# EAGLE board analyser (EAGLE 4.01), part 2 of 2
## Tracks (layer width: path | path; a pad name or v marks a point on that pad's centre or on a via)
1A0
  Top 0.406: IC5.9 108.97,43.47 109.45,43 109.45,32.04 108.81,31.41 96.59,31.41 95.79,32.2 95.79,35.22 96.43,35.85 97.7,35.85 | 97.7,35.85 | 97.7,35.85 IC9.2
1A1
  Top 0.406: 101.35,46.49 108.18,46.49 | IC9.5 97.7,39.66 98.97,39.66 100.56,41.25 100.56,45.7 101.35,46.49 | 101.35,46.49 | 108.18,46.49 | IC5.7 112.46,42.2 108.18,46.49
1A2
  Top 0.406: IC9.11 93.41,40.93 95,39.35 95,31.88 96.27,30.61 109.13,30.61 110.24,31.73 110.24,38.87 112.3,40.93 113.73,40.93 IC5.6
1A3
  Top 0.406: IC9.14 93.09,37.12 94.21,36.01 94.21,31.57 95.95,29.82 109.45,29.82 111.03,31.41 111.03,38.23 | IC5.5 112.46,39.66 111.03,38.23 | 111.03,38.23
1A4
  Top 0.406: IC10.2 84.52,34.27 86.11,32.68 86.11,30.46 87.54,29.03 109.76,29.03 111.83,31.09 111.83,36.65 112.3,37.12 113.73,37.12 | 113.73,37.12 | 113.73,37.12 IC5.3
1A5
  Top 0.406: IC10.5 80.71,38.08 80.39,37.76 80.39,32.2 84.36,28.23 112.94,28.23 115.95,31.25 115.95,35.22 115.32,35.85 IC5.2 | IC5.2 113.57,35.85 | IC5.2
1A6
  Top 0.406: IC10.11 71.98,39.35 70.08,37.44 70.08,32.52 73.25,29.34 81.98,29.34 83.89,27.44 113.26,27.44 116.75,30.93 | IC5.4 113.73,38.39 | IC5.4 | IC5.4 115.32,38.39 116.75,36.96 116.75,30.93 | 116.75,30.93
1A7  (via drill 0.61 pad 1.68)
  Top 0.406: IC10.14 77.54,35.54 78.65,34.42 v78.65,30.93 | v105.16,38.39 IC5.13
  Bottom 0.406: v105.16,38.39 106.75,36.81 106.75,34.58 102.3,30.14 79.44,30.14 v78.65,30.93
1A8  (via drill 0.61 pad 1.68)
  Top 0.406: IC5.12 106.43,39.66 104.84,41.25 103.89,41.25 | v82.14,82.53 | IC11.2 83.25,81.42 v82.14,82.53 | 103.89,41.25 v103.73,41.25 | v103.73,41.25 | v103.73,41.25 | 103.89,41.25 v103.73,41.25
  Bottom 0.406: v103.73,41.25 105.16,42.68 105.16,60.94 83.57,82.53 v82.14,82.53
1A9  (via drill 0.61 pad 1.68)
  Top 0.406: IC5.14 106.27,37.12 105.95,36.81 104.68,36.81 103.73,37.76 103.73,38.23 v102.3,39.66 | IC11.5 82.94,77.61 82.46,77.13 82.46,72.21 v83.09,71.57
  Bottom 0.406: v83.09,71.57 84.52,70.14 94.84,70.14 104.37,60.62 104.37,44.11 | 104.37,44.11 | 104.37,44.11 | v102.3,39.66 102.3,42.04 104.37,44.11
1A10  (via drill 0.61 pad 1.68)
  Top 0.406: v105.16,35.38 105.64,35.85 IC5.15 | IC11.11 92.14,76.34 v93.09,77.29
  Bottom 0.406: v93.09,77.29 94.52,75.86 94.52,72.68 105.95,61.25 105.95,41.25 103.73,39.03 103.73,36.81 v105.16,35.38 | v105.16,35.38
1A11  (via drill 0.61 pad 1.68)
  Top 0.406: IC5.1 112.94,34.58 112.94,33 v113.89,32.04 | IC11.14 92.46,80.15 v93.09,79.51 | IC6.10 79.6,94.59 80.08,95.07 82.14,95.07 83.41,93.8 v83.41,87.61
  Bottom 0.406: v113.89,32.04 115,33.15 115,40.46 | v83.41,87.61 84.05,88.24 90.87,88.24 93.09,86.02 v93.09,79.51 119.29,53.32 119.29,44.74 115,40.46 | 115,40.46
1A12
  Top 0.406: 71.98,81.41 | 71.98,81.41 IC12.2 | 71.98,81.41 69.92,81.41 66.74,84.59 66.74,88.56 68.81,90.62 79.92,90.62 80.87,91.57 IC6.9 | IC6.9 80.87,93.32 | IC6.9
1A13
  Top 0.406: 71.66,77.6 | IC12.5 71.66,77.6 | 71.66,77.6 73.25,77.6 75.47,79.83 75.47,83.64 76.74,84.91 78.81,84.91 79.6,85.7 IC6.7
1C0
  Top 0.406: IC17.16 58.32,49.82 49.28,40.77 43.41,40.77 40.62,37.99 IC16.12
1C1
  Top 0.406: IC17.15 57.52,50.13 48.96,41.57 43.09,41.57 39.84,38.32 IC16.13
1D0
  Top 0.406: IC13.11 | IC13.11 92.46,54.27 91.03,55.7 67.06,55.7 64.84,53.47 62.3,53.47 60.72,55.05 IC17.19 | IC13.11 92.46,51.41 94.68,49.19 97.54,49.19 108.18,59.82 113.73,59.82 119.76,65.86 IC14.18 | 109.6,71.73 116.75,71.73 119.76,68.71 IC14.18 | 109.6,71.73 | IC15.4 109.6,71.73 | IC14.18
1D1
  Top 0.406: IC13.12 | IC13.12 93.73,54.27 91.51,56.49 66.74,56.49 64.52,54.27 62.61,54.27 61.52,55.36 IC17.20 | IC13.12 93.73,51.41 95.16,49.98 97.22,49.98 107.86,60.62 113.26,60.62 118.49,65.86 118.49,67.44 | IC15.3 105.48,70.46 105.95,70.94 109.92,70.94 | 109.92,70.94 116.27,70.94 118.49,68.71 118.49,67.44 | 109.92,70.94 | IC14.17 118.49,67.29 | 118.49,67.44 IC14.17 | IC14.17
1D2
  Top 0.406: 64.2,55.06 66.42,57.28 91.98,57.28 95,54.27 IC13.13 | IC13.13 | IC13.13 95,51.41 95.63,50.78 96.9,50.78 107.54,61.41 112.78,61.41 117.22,65.86 117.22,67.44 | IC15.2 105.48,69.19 106.43,70.14 110.24,70.14 | 110.24,70.14 115.8,70.14 117.22,68.71 117.22,67.44 | 110.24,70.14 | IC14.16 117.22,67.29 | 117.22,67.44 IC14.16 | IC14.16 | IC17.21 62.32,55.67 62.93,55.06 64.2,55.06 | 64.2,55.06
1D3
  Top 0.406: 96.27,61.89 92.46,58.08 63.12,58.08 IC17.22 | IC15.1 105.48,67.92 106.91,69.35 110.56,69.35 | 110.56,69.35 115.32,69.35 115.95,68.71 IC14.15 | 110.56,69.35 | 96.27,61.89 106.91,61.89 107.22,62.21 112.3,62.21 115.95,65.86 IC14.15 | 96.27,61.89 IC13.15 | IC14.15
1D4
  Top 0.406: 103.25,63.16 99.76,66.65 99.76,68.87 99.44,69.19 97.86,69.19 | 103.25,63.16 | IC14.14 114.68,65.86 111.83,63 103.41,63 103.25,63.16 | 97.86,69.19 96.59,69.19 95,67.6 IC13.16 95,61.89 91.95,58.84 IC17.23 | 97.86,69.19 98.02,69.19 IC15.15 97.86,69.19
1D5
  Top 0.406: 98.17,70.46 IC15.14 | 98.17,70.46 96.59,70.46 93.73,67.6 IC13.17 93.73,61.89 91.48,59.64 IC17.24 | 100.56,69.35 99.44,70.46 98.17,70.46 | IC14.13 113.41,65.86 111.35,63.79 103.73,63.79 100.56,66.97 100.56,69.35 | 100.56,69.35
1D6
  Top 0.406: IC15.13 98.17,71.73 | 98.17,71.73 96.59,71.73 92.46,67.6 IC13.18 92.46,61.89 91.01,60.44 IC17.25 | 102.94,65.7 101.35,67.29 101.35,69.83 99.44,71.73 98.17,71.73 | 102.94,65.7 | IC14.12 112.14,65.86 110.87,64.59 104.05,64.59 102.94,65.7
1D7
  Top 0.406: IC15.12 98.17,73 | 98.17,73 96.59,73 91.19,67.6 IC13.19 91.19,61.89 90.54,61.24 IC17.26 | 98.17,73 99.44,73 102.14,70.3 102.14,67.6 104.37,65.38 110.4,65.38 110.87,65.86 110.87,67.29 | 110.87,67.29 | 110.87,67.29 IC14.11
1G0
  Top 0.406: CON2.10 | CON2.10 | CON2.10 41.66,5.06 42.93,6.33 42.93,7.28 41.42,8.79 IC16.30
1G1
  Top 0.406: CON2.11 | CON2.11 | CON2.11 44.2,7.12 42.22,9.1 IC16.31
1G2
  Top 0.406: CON2.12 | CON2.12 | CON2.12 46.74,5.69 43.02,9.41 IC16.32
1G3
  Top 0.406: CON2.13 | CON2.13 | CON2.13 49.28,5.69 47.06,7.91 47.06,10.45 45.88,11.63 IC16.1
1G4
  Top 0.406: CON2.14 | CON2.14 | CON2.14 51.82,4.26 47.85,8.23 47.85,10.77 46.19,12.43 IC16.2
1G5
  Top 0.406: CON2.15 | CON2.15 | CON2.15 54.36,4.26 57.85,7.75 57.85,19.66 54.36,23.15 46.74,23.15 43.02,19.43 IC16.9
1G6
  Top 0.406: CON2.16 | CON2.16 | CON2.16 56.9,5.69 58.65,7.44 58.65,19.98 54.68,23.95 46.42,23.95 | 46.42,23.95 | IC16.10 42.22,19.74 46.42,23.95
1G7
  Top 0.406: CON2.17 | CON2.17 | CON2.17 59.44,20.3 54.99,24.74 46.1,24.74 41.42,20.05 IC16.11
2A0  (via drill 0.61 pad 1.68)
  Top 0.406: 48.64,76.97 48.64,85.22 52.93,89.51 54.2,89.51 | 54.2,89.51 | 54.2,89.51 IC8.2 | IC9.3 v100.08,37.12 | IC15.11 99.44,74.27 100.71,75.54 | v100.08,37.12 | 48.64,76.97 | 48.64,76.97 51.82,73.79 59.76,73.79 v60.71,72.84 60.72,72.84 IC17.37 | 100.71,75.54 | v100.08,79.51 100.71,78.87 100.71,75.54
  Bottom 0.406: 87.06,44.27 85.16,46.17 77.85,46.17 73.73,50.3 73.73,51.41 73.09,52.05 73.09,68.71 70.23,71.57 61.98,71.57 v60.71,72.84 60.71,75.38 69.28,83.95 70.23,83.95 71.19,84.91 71.19,86.65 75.16,90.62 | v100.08,37.12 | v100.08,37.12 100.08,39.66 95.48,44.27 87.06,44.27 | v100.08,79.51 100.08,82.37 91.82,90.62 75.16,90.62 | 75.16,90.62 | 87.06,44.27
2A1  (via drill 0.61 pad 1.68)
  Top 0.406: 54.36,88.24 | 54.36,88.24 IC8.3 | 54.36,88.24 52.93,88.24 49.44,84.75 49.44,77.29 52.14,74.59 61.82,74.59 61.98,74.43 | IC9.6 98.97,40.93 99.76,41.73 99.76,44.43 | 99.76,44.43 99.13,45.06 v98.17,45.06 | 61.98,74.43 v62.93,73.48 62.93,71.41 61.52,70 IC17.36 | 61.98,74.43 | v98.65,81.1 98.65,78.4 99.92,77.13 99.92,76.02 99.45,75.54 | 99.45,75.54 IC15.10 | 99.76,44.43 | 99.45,75.54 99.44,75.54
  Bottom 0.406: v98.65,81.1 98.65,82.68 91.51,89.83 75.47,89.83 71.98,86.34 71.98,84.59 70.55,83.16 69.6,83.16 62.93,76.49 v62.93,73.48 64.04,72.37 70.55,72.37 | 70.55,72.37 | 70.55,72.37 73.89,69.03 73.89,52.36 74.52,51.73 74.52,50.62 78.17,46.97 85.47,46.97 87.38,45.06 v98.17,45.06 | v98.17,45.06
2A2  (via drill 0.61 pad 1.68)
  Top 0.406: 50.23,77.6 50.23,84.27 52.93,86.97 IC8.4 | IC8.4 | IC9.10 93.25,42.2 93.73,42.68 93.73,44.27 92.78,45.22 91.51,45.22 v90.08,46.65 | 50.23,77.6 | 50.23,77.6 52.45,75.38 63.88,75.38 v65.15,74.11 | v97.22,79.51 96.43,78.72 96.43,77.13 96.75,76.81 IC15.9 | IC15.9 98.02,76.81 | IC15.9 | 65.15,72.52 | IC17.35 62.32,69.69 65.15,72.52 | v65.15,74.11 65.15,72.52 | v65.15,74.11
  Bottom 0.406: v97.22,79.51 97.22,83 91.19,89.03 75.79,89.03 72.77,86.02 72.77,84.27 70.87,82.37 69.92,82.37 65.15,77.6 v65.15,74.11 66.11,73.16 70.87,73.16 74.68,69.35 74.68,52.68 75.31,52.05 75.31,50.93 78.49,47.76 85.79,47.76 86.9,46.65 v90.08,46.65
2A3  (via drill 0.61 pad 1.68)
  Top 0.406: IC8.5 52.93,85.7 51.03,83.8 51.03,77.92 52.77,76.18 65.15,76.18 67.06,74.27 v67.06,70.14 65.63,68.71 64.36,68.71 63.73,68.08 63.12,68.08 IC17.34 | IC4.11 70.39,19.34 67.69,22.04 67.69,46.01 v72.3,50.62 | IC9.13 | v88.97,38.39 IC9.13
  Bottom 0.406: 84.84,45.38 77.54,45.38 v72.3,50.62 72.3,68.4 70.55,70.14 v67.06,70.14 | 84.84,45.38 | v88.97,38.39 88.97,41.25 84.84,45.38
2A4  (via drill 0.61 pad 1.68)
  Top 0.406: IC8.6 52.93,84.43 51.82,83.32 51.82,78.24 | IC4.10 70.39,20.61 68.49,22.52 68.49,44.58 70.23,46.33 | 64.2,67.44 64.68,67.92 v67.06,67.92 68.49,69.35 68.49,73.95 65.47,76.97 53.09,76.97 51.82,78.24 | 70.23,46.33 v72.3,48.39 | 70.23,46.33 | 82.14,35.54 | 82.14,35.54 IC10.3 | 51.82,78.24 | v86.11,36.96 | 82.14,35.54 84.68,35.54 v86.11,36.96 | 64.2,67.44 | IC17.33 64.2,66.84 64.2,67.44
  Bottom 0.406: v67.06,67.92 68.49,69.35 70.23,69.35 71.5,68.08 71.5,52.05 70.87,51.41 70.87,49.82 v72.3,48.39 | v67.06,67.92 | v72.3,48.39 | 83.89,42.2 86.11,39.98 v86.11,36.96 | v72.3,48.39 73.89,46.81 73.89,45.7 77.38,42.2 83.89,42.2 | v72.3,48.39 | v86.11,36.96 | 83.89,42.2
2A5  (via drill 0.61 pad 1.68)
  Top 0.406: IC8.7 52.93,83.16 52.61,82.84 52.61,78.56 53.41,77.76 65.79,77.76 69.28,74.27 v69.28,67.92 67.85,66.49 66.74,66.49 66.29,66.04 IC17.32 | IC4.9 70.39,21.88 69.28,22.99 69.28,43.16 70.23,44.11 | 70.23,44.11 v72.3,46.17 | 70.23,44.11 | v84.36,39.35 IC10.6 | v84.36,39.35
  Bottom 0.406: 70.71,52.36 70.08,51.73 70.08,48.39 v72.3,46.17 | v72.3,46.17 | 70.71,52.36 | v69.28,67.92 70.71,66.49 70.71,52.36 | v72.3,46.17 77.06,41.41 83.57,41.41 84.36,40.62 v84.36,39.35
2A6  (via drill 0.61 pad 1.68)
  Top 0.406: IC10.10 73.73,40.62 72.3,42.04 v72.3,43.95 | v69.28,65.7 67.06,65.7 66.6,65.24 IC17.31
  Bottom 0.406: v72.3,43.95 70.39,45.85 | 70.39,45.85 | v69.28,65.7 69.28,62.36 69.92,61.73 69.92,52.68 69.28,52.05 69.28,46.97 70.39,45.85
2A7  (via drill 0.61 pad 1.68)
  Top 0.406: v73.73,36.81 IC10.13 | v73.73,36.81 | IC17.30 66.09,64.44 66.27,64.27 v67.69,64.27
  Bottom 0.406: v73.73,36.81 68.49,42.04 68.49,52.52 69.12,53.16 69.12,61.41 67.69,62.84 v67.69,64.27
2A8
  Top 0.406: IC8.19 62.93,89.51 62.3,90.15 62.3,95.07 63.09,95.86 82.46,95.86 86.59,91.73 86.59,84.43 86.9,84.11 86.9,81.1 85.95,80.14 84.52,80.14 84.52,80.15 IC11.3
2A9
  Top 0.406: IC8.18 63.09,88.24 61.34,89.99 61.34,95.23 62.77,96.65 82.78,96.65 87.38,92.05 87.38,84.75 | 87.38,84.75 87.7,84.43 | IC11.6 84.52,76.34 84.52,76.33 85.95,76.33 87.7,78.08 87.7,84.43 | 87.38,84.75 87.7,84.43
2A10  (via drill 0.61 pad 1.68)
  Top 0.406: IC8.17 63.09,86.97 60.55,89.51 60.55,95.54 62.46,97.45 83.09,97.45 88.81,91.73 v88.81,85.38 | IC11.10 v93.09,75.07 v93.09,75.06
  Bottom 0.406: v93.09,75.06 88.81,79.35 v88.81,85.38
2A11
  Top 0.406: IC8.16 64.36,85.7 | IC8.16 | IC8.16 63.25,85.7 59.76,89.19 59.76,95.86 62.14,98.24 83.41,98.24 90.24,91.42 90.24,84.75 88.81,83.32 88.81,79.35 89.28,78.88 IC11.13
2A12
  Top 0.406: 71.98,80.14 IC12.3 70.08,80.14 | 70.08,80.14 | IC8.15 65.79,84.43 70.08,80.14
2A13
  Top 0.406: IC8.14 65.95,83.16 66.74,82.37 66.74,77.92 68.33,76.33 IC12.6
2D0
  Top 0.406: CON1.11 | CON1.11 | IC14.2 | CON1.11 127.38,88.08 121.03,81.73 IC14.2
2D1
  Top 0.406: IC14.3 119.76,82.21 | CON1.10 | CON1.10 | CON1.10 124.84,88.08 119.76,83 119.76,82.21 | 119.76,82.21
2D2
  Top 0.406: IC14.4 118.49,82.21 | CON1.9 | CON1.9 | CON1.9 122.3,88.08 118.49,84.27 118.49,82.21 | 118.49,82.21
2D3
  Top 0.406: IC14.5 117.22,82.53 | CON1.8 | CON1.8 | CON1.8 119.76,88.08 117.22,85.54 117.22,82.53 | 117.22,82.53
2D4
  Top 0.406: IC14.6 115.95,82.53 | CON1.7 | CON1.7 | CON1.7 117.22,88.08 115.95,86.81 115.95,82.53 | 115.95,82.53
2D5
  Top 0.406: IC14.7 114.68,82.53 | CON1.6 | CON1.6 | 114.68,82.53 | 114.68,82.53 CON1.6
2D6
  Top 0.406: IC14.8 113.41,82.53 | CON1.5 | CON1.5 | CON1.5 112.14,88.08 113.41,86.81 113.41,82.53 | 113.41,82.53
2D7
  Top 0.406: IC14.9 112.14,83.16 | CON1.4 | CON1.4 | CON1.4 109.6,88.08 112.14,85.54 112.14,83.16 | 112.14,83.16
3A0  (via drill 0.61 pad 1.68)
  Top 0.406: 94.84,41.25 94.84,45.06 93.25,46.65 v92.14,46.65 | v92.14,49.51 91.19,50.46 IC13.10 | IC9.4 96.27,38.39 95.79,38.87 95.79,40.3 94.84,41.25 | 94.84,41.25
  Bottom 0.406: v92.14,46.65 v92.14,49.51
3A1
  Top 0.406: IC9.7 96.27,42.2 95.63,42.84 95.63,45.38 92.94,48.08 91.51,48.08 89.92,49.66 IC13.9
3A2
  Top 0.406: IC9.9 90.24,43.47 88.65,45.06 IC13.8
3A3
  Top 0.406: IC9.12 90.24,39.66 87.38,42.52 IC13.7
3A4
  Top 0.406: IC10.4 83.89,36.81 86.11,39.03 IC13.6
3A5
  Top 0.406: IC10.7 83.57,40.62 84.84,41.89 IC13.5
3A6  (via drill 0.61 pad 1.68)
  Top 0.406: IC13.4 83.57,46.65 v80.71,43.79 | IC10.9 77.38,41.89 77.85,42.36 v77.85,43.79
  Bottom 0.406: v77.85,43.79 v80.71,43.79
3A7
  Top 0.406: IC10.12 77.54,38.08 79.28,39.82 79.28,44.58 | 79.28,44.58 82.3,47.6 IC13.3 | 79.28,44.58
3A8
  Top 0.406: IC11.4 84.36,78.88 84.36,78.87 82.93,78.87 81.66,77.6 81.66,68.71 83.57,66.81 IC13.25
3A9
  Top 0.406: IC13.24 84.84,66.81 87.06,69.03 87.06,73.79 85.79,75.06 84.36,75.06 84.36,75.07 IC11.7
3A10
  Top 0.406: IC13.21 88.65,65.06 88.81,65.22 88.81,66.49 88.65,66.65 88.65,73.16 89.28,73.79 90.55,73.79 90.56,73.8 IC11.9
3A11
  Top 0.406: IC13.23 86.11,65.06 85.95,65.22 85.95,66.81 87.86,68.71 87.86,76.18 89.28,77.6 90.55,77.6 90.56,77.61 IC11.12
3A12  (via drill 0.61 pad 1.68)
  Top 0.406: IC13.2 81.03,54.27 80.39,54.9 76.9,54.9 v76.11,54.11 | 71.82,78.87 | 71.82,78.87 IC12.4 | v69.28,78.87 71.82,78.87
  Bottom 0.406: v76.11,54.11 75.47,54.74 75.47,69.67 69.28,75.86 v69.28,78.87
3A13
  Top 0.406: IC13.26 82.3,66.65 79.44,69.51 75.79,69.51 74.68,70.62 74.68,73.95 73.57,75.06 71.82,75.06 IC12.7
+5V
  Bottom 0.406: C44.P | C44.P 129.45,36.41 CON5.1 137.72,36.47 | C43.2 127.23,36.81 | C43.2 | C44.P 127.23,36.33 C43.2 | 137.72,36.47 137.7,36.49 | 137.86,36.33 137.72,36.47
  Bottom 0.813: CON2.19 64.52,3.79 66.11,5.37 68.49,5.37 69.92,3.94 133.42,3.94 137.86,8.39 137.86,36.33
AREF  (1 unrouted)
CD
  Top 0.406: CON2.8 | CON2.8 | CON2.8 35.31,3.79 35.31,6.01 38.24,8.94 IC16.26
CE
  Top 0.406: CON2.7 | CON2.7 | CON2.7 34.04,5.85 37.44,9.25 IC16.25
CL  (via drill 0.61 pad 1.68)
  Top 0.406: IC5.11 106.43,40.93 104.84,42.52 104.84,43.95 | v64.68,48.39 67.06,48.39 70.71,52.05 73.09,52.05 75.31,49.82 v80.87,49.82 | 104.84,43.95 | v101.98,45.06 103.73,45.06 104.84,43.95 | v66.74,90.62 67.54,91.42 78.01,91.42 78.33,91.73 IC6.11 | IC6.11 | v41.98,68.87 41.98,70.78 42.93,71.73 44.2,71.73 46.9,69.03 v46.9,67.29 48.94,65.24 IC17.3
  Bottom 0.406: v80.87,49.82 82.14,48.55 85.79,48.55 88.17,50.93 96.11,50.93 v101.98,45.06 | v66.74,90.62 | v66.74,90.62 64.2,90.62 46.9,73.32 v46.9,67.29 46.9,59.82 58.33,48.39 v64.68,48.39 | v41.98,68.87 SPI2.3 | v101.98,45.06 | v101.98,45.06
DE  (via drill 0.61 pad 1.68)
  Top 0.406: IC14.1 122.3,73.79 121.03,72.52 | 121.03,67.29 | 121.03,67.29 IC14.19 | 121.03,72.52 121.03,67.29 | 121.03,72.52 110.87,72.52 v108.33,75.06 | v43.56,76.02 44.83,76.02 45.79,75.06 45.79,73.64 50.07,69.35 51.5,69.35 52.45,70.3 55.15,70.3 55.92,69.53 IC17.43
  Bottom 0.406: v108.33,75.06 108.33,77.45 92.78,93 64.36,93 47.37,76.02 v43.56,76.02
EXF
  Top 0.406: IC4.4 76.43,16.8 73.73,19.5 73.73,24.26 78.01,28.55 81.66,28.55 83.57,26.65 113.57,26.65 121.99,35.06 | CON1.12 129.92,53.32 121.99,45.38 121.99,35.06 | 121.99,35.06
F1  (via drill 0.61 pad 1.68)
  Top 0.406: IC3.13 86.11,16.8 85.47,16.17 v83.89,16.17 | v68.96,18.07 IC4.12 | v68.96,18.07
  Bottom 0.406: v68.96,18.07 70.87,16.17 v83.89,16.17
F1K  (via drill 0.61 pad 1.68)
  Top 0.406: v95.95,19.98 | v95.95,19.98 97.86,18.07 IC2.12 | v108.33,15.53 IC2.3 | v108.33,15.53 | IC4.15 70.55,14.26 69.6,13.31 v67.38,13.31
  Bottom 0.406: v108.33,15.53 100.4,15.53 v95.95,19.98 95.32,20.61 79.76,20.61 78.81,21.57 67.69,21.57 64.84,18.71 64.84,14.9 66.42,13.31 v67.38,13.31
F1M  (via drill 0.61 pad 1.68)
  Top 0.406: 118.18,16.8 | 118.18,16.8 IC1.4 | 118.18,16.8 119.45,16.8 v120.4,17.76 | IC4.3 79.76,15.53 80.39,16.17 v80.39,22.2
  Bottom 0.406: QG1.8 122.62,28.23 120.4,26.01 v120.4,17.76 112.78,17.76 107.06,23.47 87.38,23.47 86.11,24.74 82.93,24.74 v80.39,22.2
F10  (via drill 0.61 pad 1.68)
  Top 0.406: v95.95,15.53 IC3.3 | v95.95,15.53 | IC4.13 69.92,16.8 69.6,16.49 v67.38,16.49 | v85.16,18.07 IC3.12 | v85.16,18.07
  Bottom 0.406: v95.95,15.53 93.41,18.07 v85.16,18.07 | v67.38,16.49 67.38,18.71 68.33,19.66 78.17,19.66 79.76,18.07 v85.16,18.07 | v85.16,18.07
F10K  (via drill 0.61 pad 1.68)
  Top 0.406: IC2.4 107.38,16.8 v108.33,17.76 109.29,16.8 IC1.13 | v85.16,22.2 82.3,19.34 82.3,15.53 79.76,12.99 78.17,12.99 IC4.1
  Bottom 0.406: v108.33,17.76 104.52,21.57 85.79,21.57 v85.16,22.2
F100  (via drill 0.61 pad 1.68)
  Top 0.406: IC3.4 95,16.8 v95.95,17.76 96.9,16.8 IC2.13 | IC4.14 69.6,15.53 v68.96,14.9
  Bottom 0.406: v95.95,17.76 94.05,19.66 79.44,19.66 78.49,20.61 68.01,20.61 65.79,18.39 65.79,15.85 66.74,14.9 v68.96,14.9
F100K  (via drill 0.61 pad 1.68)
  Top 0.406: 117.86,15.53 | 117.86,15.53 IC1.3 v120.4,15.53 | IC1.12 110.24,18.07 v108.33,19.98 | v120.4,15.53 | IC4.2 79.76,14.26 81.35,15.85 81.35,20.93 v82.62,22.2
  Bottom 0.406: v120.4,15.53 112.78,15.53 v108.33,19.98 105.79,22.52 87.06,22.52 85.79,23.79 84.2,23.79 v82.62,22.2
FD1A
  Top 0.406: IC1.1 116.91,12.99 115.95,13.95 115.95,19.66 116.91,20.61 117.86,20.61 | 117.86,20.61 | 117.86,20.61 IC1.7
FD1B
  Top 0.406: IC1.15 113.1,14.26 114.05,15.22 114.05,20.93 113.1,21.88 111.83,21.88 | 111.83,21.88 | 111.83,21.88 IC1.9
FD2A
  Top 0.406: IC2.7 104.84,20.61 103.89,19.66 103.89,13.95 104.84,12.99 106.11,12.99 | 106.11,12.99 | 106.11,12.99 IC2.1
FD2B
  Top 0.406: IC2.15 101.03,14.26 101.98,15.22 101.98,20.93 101.03,21.88 99.76,21.88 | 99.76,21.88 | 99.76,21.88 IC2.9
FD3A
  Top 0.406: IC3.1 92.46,12.99 91.51,13.95 91.51,19.66 92.46,20.61 93.73,20.61 | 93.73,20.61 | 93.73,20.61 IC3.7
FD3B
  Top 0.406: IC3.15 88.65,14.26 89.6,15.22 89.6,20.93 88.65,21.88 87.38,21.88 | 87.38,21.88 | 87.38,21.88 IC3.9
FRQ  (via drill 0.61 pad 1.68)
  Top 0.406: IC4.5 76.43,18.07 74.52,19.98 74.52,23.95 77.22,26.65 v79.28,26.65 | v107.54,45.06 106.43,45.06 105.95,44.58 | v117.86,47.76 | IC7.1 117.86,49.66 v117.86,47.76 | IC5.10 106.43,42.2 105.95,42.68 105.95,44.58 | 105.95,44.58
  Bottom 0.406: v79.28,26.65 81.98,29.34 102.62,29.34 107.54,34.27 v107.54,45.06 110.24,47.76 v117.86,47.76
FS  (via drill 0.61 pad 1.68)
  Top 0.406: IC16.28 39.84,7.37 v38.17,5.69
  Bottom 0.406: v38.17,5.69 39.44,4.42 61.34,4.42 61.98,3.79 CON2.18 | CON2.18 | CON2.18
GND  (via drill 0.61 pad 1.68)
  Top 0.406: 102.94,12.68 102.94,21.88 | 102.94,12.68 | IC4.8 | IC2.14 100.08,15.53 | IC2.14 | IC1.14 112.14,15.53 | IC1.14 | IC1.14 110.56,15.53 108.97,13.95 108.33,13.95 | 102.94,21.88 IC2.8 | v28.64,84.75 27.69,83.8 IC18.10 27.69,79.51 | IC3.2 95,14.26 95.32,13.95 95.95,13.95 | IC2.14 98.17,15.53 96.59,13.95 95.95,13.95 | IC2.2 107.38,14.26 107.7,13.95 108.33,13.95 | 90.55,21.88 90.55,12.68 | 90.55,12.68 | 90.55,21.88 | C1.2 49.81,17.54 54.68,12.68 54.68,6.64 54.04,6.01 51.5,6.01 50.87,6.64 50.87,12.04 49.81,13.1 C2.1 | C2.1 48.64,12.99 | C20.1 89.7,36.39 90.24,35.85 91.67,35.85 | IC8.10 55.63,79.35 55.63,80.62 | 55.63,81.89 55.63,80.62 | 55.63,80.62 IC8.9 | 55.63,80.62 | 55.63,81.89 56.42,82.68 56.42,90.15 55.79,90.78 54.2,90.78 | C18.1 | 72.46,10.77 C18.1 | C38.- 72.62,8.55 | 72.46,10.77 72.46,8.55 C38.- | C38.- | v83.89,10.77 72.46,10.77 | v83.89,10.77 | 60.71,53 C33.1 60.71,52.84 | C31.1 44.68,63.48 | C31.1 44.68,62.84 42.29,62.84 | 42.29,62.84 | 42.29,62.84 C40.- | C32.1 71.5,64.59 | C32.1 | C32.1 71.5,64.27 70.55,64.27 69.12,62.84 IC17.28 59.92,62.84 | C36.- 73.7,65.67 72.51,64.48 C32.1 | 116.43,43.16 C28.1 116.43,43.47 IC5.8 112.3,43.47 108.33,47.44 100.56,47.44 | 119.45,58.55 IC7.8 116.91,58.55 | 119.45,58.55 | 116.91,58.55 116.91,59.67 119.45,62.21 C26.1 121.83,62.21 v121.83,64.27 | 116.91,58.55 IC7.9 113.1,58.55 | 116.91,58.55 | IC12.13 76.27,78.87 76.27,80.14 | IC6.8 80.87,85.7 79.28,84.11 77.06,84.11 76.27,83.32 76.27,81.41 | 80.08,81.41 C23.1 | 103.73,81.26 101.98,83 96.75,83 95.16,81.41 | 73.25,73.79 IC12.8 | 21.34,79.51 IC18.15 | 27.69,79.51 21.34,79.51 | 21.34,79.51 17.53,79.51 C14.1 C12.2 17.53,75.22 | 27.69,79.51 28.96,78.24 IC18.8 28.96,68.87 C13.2 29.28,68.87
  Top 0.406: C3.2 42.29,57.92 | C3.2 C4.1 | C3.2 40.29,57.86 38.64,59.51 38.64,62.84 | 38.64,62.84 42.29,62.84 | 38.64,62.84 38.64,82.84 45.95,90.15 45.95,102.53 | 90.55,21.88 88.49,23.95 79.44,23.95 78.81,23.31 76.58,23.31 76.27,22.99 76.27,22.36 76.74,21.88 IC4.8 | 93.57,21.88 IC3.8 96.43,21.88 97.54,22.99 101.83,22.99 102.94,21.88 | 93.57,21.88 90.55,21.88 | 93.57,21.88 | 115,21.88 113.89,22.99 109.6,22.99 108.49,21.88 105.95,21.88 | 102.94,21.88 | 102.94,21.88 | 115,21.88 | 115,21.88 115,12.99 115.8,12.2 115.8,10.77 C15.1 | C15.1 | 127.54,10.77 127.54,8.23 | 127.54,8.71 C37.- 127.54,8.23 | C30.1 127.54,8.13 127.54,8.23 | C19.1 64.36,94.43 v66.58,94.43 | v50.39,89.99 51.18,90.78 54.2,90.78 | IC8.1 54.52,90.78 | IC8.1 | 54.2,90.78 IC8.1 | 54.2,90.78 IC8.1 | IC8.1 | IC13.20 89.92,65.06 90.08,65.22 v90.08,71.57 92.46,71.57 95.16,74.27 95.16,81.41 | 110.87,77.45 IC14.10 110.87,79.67 v109.29,81.26 | 110.87,77.45 | IC9.8 96.43,43.47 96.43,45.85 98.02,47.44 100.56,47.44 | IC11.8 85.63,73.8 v85.63,71.57 | IC10.8 83.57,41.89 84.05,42.36 84.05,43.47 83.73,43.79 v83.09,43.79 | C20.1 88.97,36.49 | C20.1 88.97,36.33 87.7,36.33 v86.11,34.74 | v71.5,36.65 73.35,34.8 C21.1 73.73,34.74 74.52,34.74 75,34.27 IC10.15 | 103.73,81.26 103.73,80.14 102.78,79.19 102.78,76.81 IC15.8 | 100.56,47.44 v100.56,49.98 109.13,58.55 113.1,58.55 | 95.16,81.41 93.09,81.41 C22.1 | C22.1 93.09,81.89 | IC11.15 93.09,81.42 C22.1 | IC13.14 96.27,55.86 97.54,57.13 98.65,57.13 | 98.65,57.13 C34.1 | v100.56,56.65 100.08,57.13 98.65,57.13 | C16.1 103.79,11.83 102.94,12.68 | C16.1 103.73,10.77 | 103.73,10.77 | 90.55,12.68 91.4,11.83 C17.1 91.35,10.77 | 95.95,13.95 v95.95,10.77 91.35,10.77
  Top 0.406: IC3.14 86.11,15.53 83.89,13.31 v83.89,10.77 | 91.35,10.77 | v120.4,10.77 C15.1 | 26.42,102.53 | 26.42,102.53 45.95,102.53 | 45.95,102.53 50.39,102.53 | 50.39,102.53 v50.39,94.43 | 50.39,102.53 131.51,102.53 136.12,97.92 136.12,55.54 140.88,50.78 140.88,28.23 | 55.63,81.89 IC8.8 | 55.63,81.89 | 76.27,80.14 IC12.14 | 91.67,35.85 | 91.67,35.85 IC9.15 | v21.34,9.5 | 127.54,10.77 135.48,10.77 140.88,16.17 140.88,28.23 | 127.54,10.77 v120.4,10.77 | 140.88,28.23 v136.12,28.23 129.77,21.88 IC1.8 118.02,21.88 | 118.02,21.88 | 118.02,21.88 115,21.88 | 118.02,21.88 | 60.71,52.84 | 60.71,52.84 60.71,53.95 59.92,54.74 IC17.18 59.92,62.84 | 26.42,102.53 17.05,102.53 11.97,97.45 11.97,63.16 5.46,56.65 5.46,15.22 11.18,9.5 v21.34,9.5 | v109.29,81.26 | 113.1,58.55 | 105.32,81.26 C25.1 | v109.29,81.26 105.32,81.26 | 105.32,81.26 103.73,81.26 | 80.08,81.41 | v82.14,80.14 81.35,80.14 80.08,81.41 | IC1.2 119.45,14.26 120.4,13.31 v120.4,10.77 | v120.4,10.77 | 140.88,28.23 | 76.27,81.41 76.27,80.14 | 76.27,81.41 IC12.15 78.01,81.41 | 76.27,81.41 | 80.08,81.41 78.01,81.41 | 78.01,81.41 | v21.34,9.5 | 73.25,73.79 | 73.25,73.79 73.89,73.16 73.89,68.71 | IC16.5 44.52,14.75 44.52,14.74 43.25,14.74 43.25,14.1 | 43.25,14.1 43.25,13.23 IC16.3 48.64,13.23 C2.1 | 43.25,14.1 43.25,14.03 IC16.21 32.61,14.03 | 59.12,62.84 IC17.39 | 59.12,62.84 59.92,62.84 | C31.1 44.68,62.84 IC17.6 59.12,62.84 | 73.89,68.71 | 73.89,68.71 78.17,68.71 79.92,66.97 v80.08,66.81 | C36.- | C36.- 73.89,68.71 | 21.82,7.6 21.97,7.6 | 21.66,7.6 21.34,7.6 21.66,7.6 | 21.66,7.6 21.82,7.6 | 21.82,7.6 C35.1 | C24.1 127.7,73 | C24.1 | C24.1 125.69,73 C39.- 125.69,73.56 | 125.69,73.56 125.71,73.56 | v125.64,77.6 125.64,73.56 125.69,73.56
  Top 0.406: 32.61,14.42 C27.1 32.61,14.03 | 32.61,14.03 32.61,13.95 30.23,13.95 | 30.23,13.95 C41.- | 30.23,13.95 27.21,13.95 24.83,11.56 23.4,11.56 v21.34,9.5 | v108.33,10.77 | v108.33,10.77 C16.1 | v108.33,10.77 | v108.33,10.77 108.33,13.95 | 108.33,13.95
  Top 0.813: CON2.2 21.34,7.6 v21.34,9.5
  Bottom 0.406: P1.2 CON2.1 | CON4.1 | CON4.1 | v28.64,84.75 26.42,86.97 CON4.1 | SPI1.6 11.18,21.09 8.48,23.79 5.46,23.79 | SW6.1 5.46,54.31 5.46,54.27 | 5.46,47.76 5.46,54.27 | C42.N 129.45,46.41 | C29.1 | C42.N | C42.N 127.23,46.49 C29.1 | C43.1 127.23,38.39 | C43.1 | C43.1 127.23,38.87 C44.N 139.45,38.87 140.88,40.3 | v66.58,94.43 v50.39,94.43 v50.39,89.99 | 121.83,77.6 v125.64,77.6 | C42.N 129.45,56.65 v121.83,64.27 121.83,77.6 | v90.08,71.57 v85.63,71.57 83.73,73.48 83.73,78.56 v82.14,80.14 | v100.56,56.65 v100.56,49.98 103.57,46.97 103.57,44.58 101.51,42.52 | 101.51,42.52 | 101.51,42.52 100.87,41.89 100.87,38.71 101.67,37.92 101.67,36.65 100.71,35.69 94.36,35.69 93.89,36.17 87.54,36.17 | v83.09,43.79 84.36,43.79 87.54,40.62 87.54,36.17 | CON1.1 101.98,86.97 107.7,81.26 v109.29,81.26 | v95.95,10.77 | v120.4,10.77 v108.33,10.77 v95.95,10.77 | 87.54,36.17 | 87.54,36.17 | 87.54,36.17 v86.11,34.74 85.79,35.06 73.09,35.06 v71.5,36.65 | 26.42,102.53 17.05,102.53 11.97,97.45 11.97,89.35 8.48,85.86 4.83,85.86 2.77,83.8 2.77,75.22 4.76,73.23 CON6.5 11.97,69.9 11.97,63.16 5.46,56.65 5.46,54.27 | v21.34,9.5 11.18,9.5 5.46,15.22 5.46,23.79 | SW5.1 5.46,30.18 5.46,30.14 | 5.46,23.79 5.46,30.14 | SPI2.6 11.18,45.22 8.64,47.76 5.46,47.76 | 5.46,30.14 5.46,47.76 | QG1.7 v136.12,28.23 | C42.N 129.53,46.41 | 26.42,102.53 32.13,102.53 | 32.13,102.53 131.51,102.53 136.12,97.92 136.12,55.54 140.88,50.78 140.88,46.49 | 32.13,102.53 CON3.1 | CON4.1 | 26.42,102.53 CON4.1 | 140.88,40.3 | 140.88,46.49 140.88,40.3 | CON5.3 137.72,46.49 140.88,46.49 | C42.N | C42.N 137.7,46.49 | CON2.1 | CON2.1 CON2.2 | CON2.1 | v50.39,89.99 | v109.29,81.26 | 121.83,77.6 118.18,81.26 v109.29,81.26
  Bottom 0.406: v80.08,66.81 81.03,67.76 91.67,67.76 98.97,60.46 98.97,58.24 v100.56,56.65 | v100.56,56.65 | CON2.2 | CON2.2 | v95.95,10.77 v83.89,10.77
  pour Bottom (isolate 0.61): 0.38,103.8 136.27,103.8 136.27,55.86 143.58,55.86 143.58,0.29 0.38,0.29
  pour Top (isolate 0.61): 0.38,103.8 136.27,103.8 136.27,55.86 143.58,55.86 143.58,0.29 0.38,0.29
LE  (via drill 0.61 pad 1.68)
  Top 0.406: IC8.11 62.46,79.35 57.22,84.59 57.22,90.46 55.79,91.89 49.91,91.89 41.98,83.95 v41.98,74.59 44.2,74.59 44.99,73.79 44.99,73.32 51.47,66.84 IC17.1 | v7.85,46.17 v15.31,46.17
  Bottom 0.406: SPI2.4 7.85,43.95 v7.85,46.17 | v41.98,74.59 41.98,72.05 39.75,69.83 39.75,68.87 17.05,46.17 v15.31,46.17
MISO  (via drill 0.61 pad 1.68)
  Top 0.406: v18.16,14.58 16.58,16.17 16.58,18.87 18.96,21.25 35.94,21.25 37.44,19.75 IC16.16
  Bottom 0.406: SPI1.1 v18.16,14.58
MOSI  (via drill 0.61 pad 1.68)
  Top 0.406: v8,22.04 | v8,22.04 36.26,22.04 38.24,20.06 IC16.15
  Bottom 0.406: SPI1.4 8,20.3 v8,22.04 | SPI1.4
N$1
  Top 0.406: C10.1 20.07,68.87 | 20.07,68.87 | 20.07,68.87 IC18.1
N$2
  Top 0.406: 22.61,71.1 21.66,70.14 21.66,68.87 C10.2 | 22.61,71.1 | 22.61,71.1 IC18.3
N$3  (via drill 0.61 pad 1.68)
  Top 0.406: 132.31,8.07 R1.1 132.31,8.23 v134.85,8.23
  Bottom 0.406: QG1.1 134.05,12.99 134.85,12.2 v134.85,8.23
N$4
  Bottom 0.406: CON6.6 4.5,82.83 3.88,82.21 3.88,77.13 5.03,75.97 CON6.4
N$5
  Bottom 0.406: CON6.8 CON6.7
N$6
  Top 0.406: C11.1 23.88,68.87 | 23.88,68.87 | 23.88,68.87 IC18.4
N$7
  Top 0.406: C11.2 25.15,68.87 | 25.15,68.87 | 25.15,68.87 IC18.5
N$8
  Top 0.406: Q1.1 52.77,19.03 48.86,19.03 C1.1 48.64,19.03 47.69,19.03 45.88,17.21 IC16.8
N$9
  Top 0.406: 42.29,59.67 C3.1 42.29,59.41 Q2.1 47.76,59.41 50.38,62.04 IC17.7
N$10
  Top 0.406: 21.34,74.43 20.7,75.06 19.75,75.06 18.48,73.79 17.53,73.79 C12.1 | 21.34,72.52 IC18.2 21.34,74.43 | 21.34,74.43
N$11
  Top 0.406: 26.42,71.1 27.37,70.14 27.37,68.87 C13.1 | 26.42,71.1 | 26.42,71.1 | 26.42,71.1 | 26.42,71.1 IC18.6
N$12
  Top 0.406: 46.42,49.82 46.42,51.41 48.64,53.63 48.64,59.03 50.85,61.24 IC17.8 | 46.42,49.82 Q2.2 | C4.2 46.42,49.61 46.42,49.82
N$13
  Top 0.406: C5.1 110.56,52.2 IC7.14
N$14
  Top 0.406: C6.1 121.99,56.01 IC7.6
N$15
  Top 0.406: 110.56,50.93 C5.2 | 110.56,50.93 | 110.56,50.93 IC7.15 | R2.1 110.5,50.93 110.56,50.93
N$16
  Top 0.406: IC7.11 114.53,56.01 115.64,54.9 115.64,47.76 | 115.64,47.76 | R5.1 115.64,47.76
N$17
  Top 0.406: IC7.7 121.99,57.28 C6.2 121.99,59.82 R3.1 121.67,59.82
N$18
  Top 0.406: IC7.3 119.45,52.2 | 121.99,52.2 R4.1 IC7.3 | IC7.3 117.86,52.2 117.86,50.93 119.29,50.93 | 119.29,50.93 | IC7.2 119.29,50.93
N$19
  Top 0.406: 48.64,14.58 47.37,14.58 45.55,16.41 IC16.7 | 48.64,14.58 C2.2 | 48.64,14.58 51.18,14.58 52.77,12.99 Q1.2
N$20
  Top 0.406: IC7.10 114.37,57.28 118.18,53.47 IC7.4 119.45,53.47
OE  (via drill 0.61 pad 1.68)
  Top 0.406: v87.38,65.86 IC13.22 | v66.27,52.68 67.22,53.63 73.73,53.63 75.31,52.05 v77.85,52.05 | v50.87,70.78 51.5,71.41 54.99,71.41 56.72,69.69 IC17.42
  Bottom 0.406: v87.38,65.86 81.19,59.67 81.19,55.38 v77.85,52.05 | v66.27,52.68 57.38,52.68 51.66,58.4 51.66,68.71 50.87,69.51 v50.87,70.78
OF  (via drill 0.61 pad 1.68)
  Top 0.406: v69.76,88.4 70.39,89.03 77.85,89.03 78.33,88.56 IC6.6 | v43.56,73.16 43.88,73.16 47.69,69.35 47.69,68.71 v49.12,67.29 50.37,66.04 IC17.2 | IC4.7 76.58,20.61 75.31,21.88 75.31,23.63 76.58,24.9 v77.7,24.9 | IC6.6 78.33,86.97 | IC6.6
  Bottom 0.406: v69.76,88.4 63.25,88.4 47.69,72.84 47.69,68.71 v49.12,67.29 | v43.56,73.16 45.15,71.57 45.15,69.51 43.09,67.44 41.66,67.44 15.62,41.41 15.62,39.98 SPI2.1 | v77.7,24.9 66.9,35.69 66.9,48.24 65.31,49.82 58.01,49.82 49.12,58.71 v49.12,67.29 | v49.12,67.29 | v49.12,67.29 v49.13,67.29
RD
  Top 0.406: CON2.6 | CON2.6 | CON2.6 31.5,9.02 34.11,11.63 IC16.24
RES16  (via drill 0.61 pad 1.68)
  Top 0.406: IC16.29 40.62,7.68 v41.34,6.96
  Bottom 0.406: v41.34,6.96 40.07,8.23 32.13,8.23 20.7,19.66 SPI1.5 | SW5.2 9.3,24.08 10.7,22.68 13.08,22.68 13.72,22.04 SPI1.5 | SPI1.5 | SPI1.5
RES17  (via drill 0.61 pad 1.68)
  Top 0.406: v43.56,70.3 43.56,68.56 | 43.56,68.56 | IC17.4 47.68,64.44 43.56,68.56
  Bottom 0.406: v43.56,70.3 41.34,70.3 40.55,69.51 40.55,68.56 15.15,43.16 SPI2.5 | SPI2.5 | SW6.2 9.3,48.21 10.7,46.81 12.93,46.81 13.72,46.01 SPI2.5
RIN  (via drill 0.61 pad 1.68)
  Top 0.406: v23.88,84.75 IC18.13
  Bottom 0.406: CON4.2 | CON4.2 | CON4.2 v23.88,84.75 23.88,83.8 21.54,81.46 CON6.2
RST
  Top 0.406: CON2.9 | CON2.9 | CON2.9 36.58,5.06 36.58,6.17 39.04,8.63 IC16.27
RXD
  Top 0.406: 25.15,82.21 IC18.12 25.15,84.59 27.69,87.13 34.2,87.13 37.37,83.95 37.37,48.87 40.71,45.54 47.37,45.54 50.23,48.39 50.23,59.19 51.48,60.44 IC17.9
SA  (via drill 0.61 pad 1.68)
  Top 0.406: IC9.1 96.75,34.58 96.75,33.47 97.22,33 v100.08,33 | IC15.7 102.46,75.54 101.51,76.49 v101.51,81.1 | IC12.1 69.76,82.68 68.17,84.27 | IC11.1 85.63,82.69 85.63,85.07 84.52,86.18 82.78,86.18 81.98,86.97 81.98,88.4 80.55,89.83 69.12,89.83 68.17,88.88 v68.17,86.97 68.17,84.27 | IC10.1 83.57,33 v84.52,32.04 | IC17.44 55.12,67.92 54.04,67.92 v53.09,68.87 | 68.17,84.27
  Bottom 0.406: v100.08,33 98.02,30.93 85.63,30.93 | 85.63,30.93 | 85.63,30.93 v84.52,32.04 83.89,32.68 71.03,32.68 67.69,36.01 67.69,53.32 66.9,54.11 57.06,54.11 53.09,58.08 v53.09,68.87 53.09,77.13 62.93,86.97 v68.17,86.97 | v101.51,81.1 101.51,82.05 92.14,91.42 74.84,91.42 70.39,86.97 v68.17,86.97 | v68.17,86.97
SCK  (via drill 0.61 pad 1.68)
  Top 0.406: 19.28,20.45 18.16,19.34 v18.16,17.12 | 19.28,20.45 | 19.28,20.45 30.86,20.45 34.11,17.21 IC16.17
  Bottom 0.406: SPI1.3 v18.16,17.12
SM  (via drill 0.61 pad 1.68)
  Top 0.406: IC13.1 79.76,51.09 79.28,50.62 75.63,50.62 73.41,52.84 69.12,52.84 67.54,51.25 v64.68,51.25 | v49.28,72.21 58.17,72.21 | 58.17,72.21 | 58.17,72.21 58.96,71.41 58.96,70.14 58.32,69.5 IC17.40
  Bottom 0.406: v49.28,72.21 49.28,69.67 50.87,68.08 50.87,58.08 | 50.87,58.08 | v64.68,51.25 57.69,51.25 50.87,58.08
SW1  (via drill 0.61 pad 1.68)
  Top 0.406: v34.99,83 35.79,82.21 35.79,48.24 40.07,43.95 48.01,43.95 55.12,51.06 IC17.12
  Bottom 0.406: v34.99,83 CON3.5 | CON3.5
SW2  (via drill 0.61 pad 1.68)
  Top 0.406: 48.33,43.16 39.75,43.16 34.99,47.92 | 34.99,47.92 | v34.2,80.78 34.99,79.99 34.99,47.92 | 48.33,43.16 | IC17.13 55.92,50.75 48.33,43.16
  Bottom 0.406: CON3.4 39.75,88.88 35.63,84.75 34.52,84.75 33.4,83.64 33.4,81.57 v34.2,80.78
SW3  (via drill 0.61 pad 1.68)
  Top 0.406: v33.4,78.56 34.2,77.76 34.2,47.6 39.44,42.36 48.64,42.36 56.72,50.44 IC17.14
  Bottom 0.406: CON3.3 37.21,87.45 35.31,85.54 34.2,85.54 32.61,83.95 32.61,79.35 v33.4,78.56
TOUT  (via drill 0.61 pad 1.68)
  Top 0.406: 22.61,83.8 v21.34,85.07 16.89,85.07 14.35,82.53 v14.35,78.72 | 22.61,82.21 IC18.14 22.61,83.8 | 22.61,83.8
  Bottom 0.406: CON4.3 | CON4.3 | v21.34,85.07 CON4.3 | CON6.3 v14.35,78.72
TR  (via drill 0.61 pad 1.68)
  Top 0.406: v52.45,52.2 51.82,52.84 51.82,58.55 52.11,58.84 IC17.11 | v106.91,73.32 105.79,73.32 105.48,73 IC15.5
  Bottom 0.406: 92.46,92.21 64.68,92.21 46.1,73.64 46.1,69.19 | 46.1,69.19 45.31,68.4 45.31,66.49 46.1,65.7 | 46.1,65.7 | 46.1,69.19 | 46.1,69.19 | v52.45,52.2 46.1,58.55 46.1,65.7 | 92.46,92.21 | v106.91,73.32 106.91,77.76 92.46,92.21
TXD
  Top 0.406: 26.42,82.21 IC18.11 26.42,84.75 28.01,86.34 33.88,86.34 36.58,83.64 36.58,48.55 40.39,44.74 47.69,44.74 51.03,48.08 51.03,58.87 51.79,59.64 IC17.10
V0
  Bottom 0.406: P1.S 24.51,5.06 26.42,3.15 CON2.4 | CON2.4 | CON2.4
VCC  (via drill 0.61 pad 1.68)  (2 unrouted)
  Top 0.406: IC1.16 113.73,12.99 114.37,12.36 114.37,10.77 | IC2.16 101.03,12.99 102.3,11.72 102.3,10.77 | IC3.16 88.65,12.99 89.92,11.72 89.92,10.77 | IC4.16 70.55,12.99 69.92,12.36 69.92,10.77 70.23,10.77 | IC3.16 87.7,12.99 | IC3.16 | v124.69,6.33 | C15.2 | 114.37,9.02 114.37,10.77 | 114.37,10.77 C15.2 | C16.2 | 102.3,9.02 102.3,10.77 | 102.3,10.77 C16.2 | C17.2 | 89.92,9.02 89.92,10.77 | 89.92,10.77 C17.2 | 70.23,10.77 C18.2 | C18.2 | 70.23,10.77 69.79,10.77 C38.+ 69.76,8.55 69.76,6.96 | 69.92,6.96 | C31.2 44.68,65.22 | C31.2 43.83,65.12 42.77,66.17 42.29,66.17 C40.+ | C31.2 44.68,65.06 45.79,65.06 47.21,63.64 IC17.5 | C32.2 71.5,62.84 | C32.2 | C32.2 71.5,62.05 | 71.5,62.05 C32.2 | 73.89,62.05 71.5,62.05 | 73.89,62.05 | IC5.16 108.65,34.58 108.65,33.47 v108.02,32.84 | 119.29,46.33 | IC7.16 114.21,49.66 114.21,47.76 | 114.21,47.76 R5.2 | 114.21,47.76 | 114.21,47.76 R5.2 | R5.2 | 114.21,47.76 R2.2 | 114.68,46.33 114.21,46.81 114.21,47.76 | IC12.16 80.08,82.68 80.08,82.84 | 73.89,62.05 C36.+ | 76.9,62.05 73.89,62.05 | IC8.20 63.09,90.78 63.09,91.57 64.2,92.69 64.36,92.69 C19.2 64.36,92.21 69.76,92.21 | 17.53,81.1 C14.2 | IC18.16 20.07,81.1 17.53,81.1 | 17.53,81.1 16.42,81.1 15.78,80.46 15.78,77.76 v14.35,76.33 | 127.54,6.33 C37.+ | v124.69,6.33 127.54,6.33 | C30.2 R1.2 | C30.2 129.45,6.48 | C30.2 127.54,6.43 127.54,6.33 | C40.+ 41.05,66.15 40.23,66.97 v40.23,78.56 | v43.72,78.56 45.47,78.56 51.03,73 58.49,73 59.92,71.57 IC17.38 | C40.+ | 88.97,34.74 C20.2 88.97,34.58 IC9.16 92.94,34.58 93.41,34.11 93.41,33.15 v92.62,32.36 | C21.2 72.67,33.1 v71.5,34.27 | C21.2 73.73,33.15 | IC10.16 73.73,33 C21.2 | v108.02,32.84 | 69.76,6.96 69.92,6.96 | 69.76,6.96 | 69.76,6.96 69.92,6.96
  Top 0.406: 80.08,82.84 C23.2 | 80.08,82.84 80.08,83.8 80.71,84.43 v83.73,84.43 | v76.9,64.75 76.9,62.05 | IC13.28 79.76,62.05 76.9,62.05 | IC6.16 71.98,92.21 69.76,92.21 | 114.68,46.33 | 119.29,46.33 114.68,46.33 | 119.29,46.33 | 119.29,46.33 | 123.89,52.2 R4.2 | 123.89,62.21 | 123.89,62.21 C26.2 | 123.89,59.82 R3.2 | 123.89,62.21 123.42,62.21 | IC14.20 122.3,67.29 | IC14.20 | 123.89,68.56 122.3,68.56 IC14.20 | IC11.16 90.55,82.68 | IC11.16 | IC11.16 91.82,82.68 92.62,83.48 93.09,83.48 C22.2 93.09,84.27 | IC15.16 96.75,67.92 96.27,67.44 96.27,66.65 98.02,64.9 v98.02,63.63 | C34.2 98.65,59.03 99.76,59.03 v100.56,59.82 | SPI1.2 | SPI1.2 | SPI1.2 | SPI1.2 | C28.2 116.43,41.57 v119.29,41.57 | 60.71,51.25 | 60.71,51.25 C33.2 | 60.71,51.25 59.76,51.25 59.12,51.89 IC17.17 | v69.76,94.43 69.76,92.21 | 105.32,84.27 C25.2 | IC16.4 45.4,14.03 45.79,14.42 45.79,15.22 45.39,15.61 IC16.6 43.33,15.61 42.53,16.41 IC16.18 32.61,16.41 32.61,16.33 | 71.5,62.05 | IC17.27 71.5,62.05 | 23.88,7.54 C35.2 23.52,7.6 23.88,7.6 | 123.89,70.78 125.69,70.78 C39.+ 125.69,71.25 127.69,71.25 | 127.69,71.25 127.7,71.25 | 127.69,71.25 C24.2 | 32.61,16.01 C27.2 32.61,16.33 | 32.61,16.33 32.61,16.49 30.23,16.49 | v27.05,16.49 30.23,16.49 | C41.+ 30.23,16.64 | C41.+ | 30.23,16.49 C41.+ | v91.67,85.38 | 75.31,6.96 | v65.15,26.01 | v102.94,34.58
  Top 0.813: v124.69,6.33 121.99,9.02 114.37,9.02 102.3,9.02 89.92,9.02 77.38,9.02 75.31,6.96 69.92,6.96 | 60.71,51.25 60.71,49.51 65.15,45.06 v65.15,26.01 65.15,10.14 68.33,6.96 69.76,6.96 | v119.29,41.57 119.29,46.33 123.89,50.93 123.89,52.2 123.89,59.82 123.89,62.21 123.89,68.56 123.89,70.78 v123.89,80.3 | v91.67,85.38 92.78,84.27 93.09,84.27 105.32,84.27 v109.29,84.27 | v14.35,76.33 14.35,63.16 18.8,58.71 18.8,34.27 v27.05,26.01 | v108.02,32.84 104.68,32.84 v102.94,34.58 | 23.88,7.54 v23.88,9.5 | CON2.3 23.88,7.6 | v23.88,13.31 v27.05,16.49
  Bottom 0.406: C29.2 127.23,44.43 | C29.2 | 127.23,43.95 C29.2 | v71.5,34.27 84.52,34.27 86.43,32.36 v92.62,32.36 | CON3.2 34.67,91.89 35.79,93 44.99,93 | 104.52,90.15 | 104.52,90.15 CON1.2 | CON1.2 104.52,90.15 | CON1.2 | 78.49,68.56 94.21,68.56 98.02,64.75 v98.02,63.63 99.13,63.63 100.56,62.21 v100.56,59.82 | SPI1.2 11.18,12.99 12.61,11.56 23.88,11.56 | SPI2.2 11.18,36.33 12.93,34.58 24.36,34.58 27.05,31.88 v27.05,26.01 | 81.98,77.29 | 79.44,82.21 | QG1.14 | QG1.14 | 123.57,41.57 | v43.72,78.56 | v65.15,26.01 | v23.88,13.31 | v27.05,16.49
  Bottom 0.813: CON5.2 131.99,41.41 C42.P 127.23,43.95 125.96,43.95 123.57,41.57 | v108.02,32.84 110.56,30.3 115,30.3 119.29,34.58 v119.29,41.57 123.57,41.57 | 123.57,41.57 123.57,33.63 127.07,30.14 127.07,17.28 124.69,14.9 QG1.14 v124.69,6.33 | v91.67,85.38 89.92,87.13 86.43,87.13 v83.73,84.43 81.66,84.43 79.44,82.21 | v76.9,64.75 78.49,66.33 78.49,68.56 78.49,72.21 81.98,75.7 81.98,77.29 | 81.98,77.29 79.44,79.83 79.44,82.21 | CON1.2 104.52,92.21 102.3,94.43 v69.76,94.43 67.85,96.34 48.33,96.34 44.99,93 44.99,79.83 v43.72,78.56 v40.23,78.56 36.9,78.56 34.67,76.33 v14.35,76.33 | 104.52,90.15 104.52,87.13 107.38,84.27 v109.29,84.27 119.92,84.27 v123.89,80.3 | v65.15,26.01 v27.05,26.01 v27.05,16.49 | v102.94,34.58 94.84,34.58 v92.62,32.36 | v23.88,13.31 23.88,11.56 v23.88,9.5
VEE  (via drill 0.61 pad 1.68)
  Top 0.406: CON2.20 67.06,4.58 65,6.64 v62.61,6.64
  Bottom 0.406: P1.1 9.27,5.37 11.18,7.28 38.8,7.28 40.71,5.37 61.34,5.37 v62.61,6.64
WC  (via drill 0.61 pad 1.68)
  Top 0.406: IC7.12 107.7,54.74 v102.94,49.98 | IC12.11 | IC12.11 76.43,76.33 75.47,75.38 75.47,70.94 76.11,70.3 78.97,70.3 v80.24,71.57
  Bottom 0.406: v102.94,49.98 103.57,50.62 103.57,60.3 94.52,69.35 82.46,69.35 v80.24,71.57
WM  (via drill 0.61 pad 1.68)
  Top 0.406: IC13.27 81.03,64.9 80.55,65.38 78.81,65.38 v76.9,67.29 | v76.9,71.73 | IC12.9 76.9,73.79 v76.9,71.73
  Bottom 0.406: v76.9,67.29 v76.9,71.73
WP  (via drill 0.61 pad 1.68)
  Top 0.406: 57.55,70.77 v57.53,70.78 v57.52,70.77 IC17.41 | v69.76,85.54 70.55,84.75 v74.2,84.75 | v74.2,84.75 | IC12.10 79.44,75.06 80.24,75.86 v80.24,76.49
  Bottom 0.406: v57.53,70.78 57.53,73.32 v69.76,85.54 | v74.2,84.75 74.2,82.53 v80.24,76.49
WR
  Top 0.406: CON2.5 | CON2.5 | CON2.5 28.96,7.6 33.8,12.43 IC16.23

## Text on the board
Top: TXD | RXD | GND | GND | VCC | SW3 | SW2 | SW1 | GND | VCC | NC | DB7 | DB6 | DB5 | DB4 | DB3 | DB2 | DB1 | DB0 | EXF | 8 Bits Logic Analyser | 2006 Tymoteusz Swieboda
Bottom: 8 Bits Logic Analyser | 2006 Tymoteusz Swieboda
